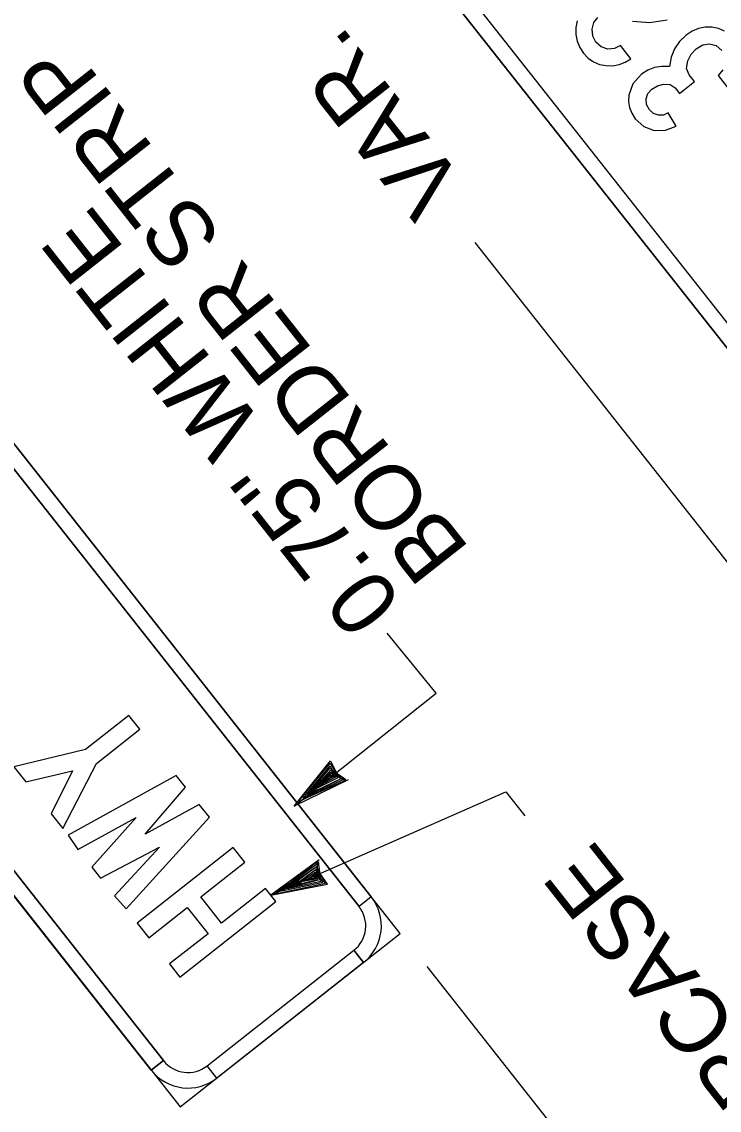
# Model space of a CAD drawing. Extents: x 672239 to 673995, y 1673540 to 1675195.
# Drawn here: x 672381.1 to 672425.9, y 1674877.9 to 1674947.8 of the extents above; entities that cross this region are included whole.
import ezdxf

# ---------------------------------------------------------------- set-up
doc = ezdxf.new("R2010")
doc.units = 0
for name, color, linetype in [('C-ALGN-SYMB', 7, 'Continuous'), ('C-ANNO-SYMB', 7, 'Continuous'), ('C-HELI-TDZM', 7, 'Continuous')]:
    doc.layers.add(name, color=color, linetype=linetype)

msp = doc.modelspace()

# ---------------------------------------------------------------- linework, layer by layer
at = {"layer": 'C-ALGN-SYMB'}
for p, q in [((672430.023, 1674908.599), (672410.262, 1674933.666)), ((672398.641, 1674897.415), (672400.961, 1674900.325)), ((672398.859, 1674897.651), (672400.942, 1674900.177)), ((672400.942, 1674900.177), (672401.284, 1674899.611)), ((672400.961, 1674900.325), (672401.353, 1674899.566)), ((672399.21, 1674897.927), (672400.94, 1674900.008)), ((672399.429, 1674898.027), (672400.983, 1674899.743)), ((672399.5, 1674898.151), (672400.942, 1674899.877)), ((672399.934, 1674898.49), (672400.928, 1674899.599)), ((672400.321, 1674898.759), (672400.892, 1674899.472)), ((672400.986, 1674899.611), (672400.48, 1674898.853)), ((672400.892, 1674899.472), (672401.174, 1674899.326)), ((672400.928, 1674899.599), (672401.281, 1674899.277)), ((672400.94, 1674900.008), (672401.078, 1674899.748)), ((672400.942, 1674899.877), (672401.623, 1674899.179)), ((672400.983, 1674899.743), (672401.443, 1674899.237)), ((672401.362, 1674899.341), (672400.986, 1674899.611)), ((672401.078, 1674899.748), (672401.623, 1674899.179)), ((672401.284, 1674899.611), (672401.955, 1674899.139)), ((672401.353, 1674899.566), (672401.595, 1674899.256)), ((672402.102, 1674899.121), (672398.641, 1674897.415)), ((672401.744, 1674899.107), (672398.901, 1674897.683)), ((672401.909, 1674899.068), (672399.061, 1674897.775)), ((672401.623, 1674899.179), (672399.429, 1674898.027)), ((672401.623, 1674899.179), (672399.5, 1674898.151)), ((672401.443, 1674899.237), (672399.934, 1674898.49)), ((672400.48, 1674898.853), (672400.227, 1674898.752)), ((672401.281, 1674899.277), (672400.321, 1674898.759)), ((672400.657, 1674899.055), (672400.922, 1674899.395)), ((672401.174, 1674899.326), (672400.657, 1674899.055)), ((672400.922, 1674899.395), (672401.004, 1674899.33)), ((672401.004, 1674899.33), (672401.362, 1674899.341)), ((672401.595, 1674899.256), (672401.909, 1674899.068)), ((672401.955, 1674899.139), (672401.735, 1674899.202)), ((672401.735, 1674899.202), (672401.744, 1674899.107)), ((672400.248, 1674893.974), (672397.128, 1674891.704)), ((672400.112, 1674893.828), (672397.642, 1674891.909)), ((672400.132, 1674893.463), (672400.112, 1674893.828)), ((672400.196, 1674893.835), (672400.15, 1674893.612)), ((672400.302, 1674893.022), (672400.196, 1674893.835)), ((672400.069, 1674893.664), (672397.486, 1674891.81)), ((672400.076, 1674893.523), (672398.036, 1674892.117)), ((672400.076, 1674893.523), (672398.179, 1674892.123)), ((672400.045, 1674893.337), (672398.681, 1674892.349)), ((672400.004, 1674893.175), (672399.1, 1674892.566)), ((672399.922, 1674892.906), (672400.099, 1674893.217)), ((672400.125, 1674892.712), (672400.004, 1674893.175)), ((672400.278, 1674892.694), (672400.045, 1674893.337)), ((672400.15, 1674893.612), (672400.069, 1674893.664)), ((672400.327, 1674892.776), (672400.076, 1674893.523)), ((672400.378, 1674892.595), (672400.076, 1674893.523)), ((672400.099, 1674893.217), (672400.163, 1674892.758)), ((672400.294, 1674893.105), (672400.132, 1674893.463)), ((672397.438, 1674891.787), (672400.643, 1674892.457)), ((672397.609, 1674891.979), (672398.357, 1674892.489)), ((672397.846, 1674891.97), (672400.493, 1674892.533)), ((672398.357, 1674892.489), (672397.846, 1674891.97)), ((672398.036, 1674892.117), (672400.278, 1674892.694)), ((672398.179, 1674892.123), (672400.378, 1674892.595)), ((672398.574, 1674892.328), (672398.961, 1674892.617)), ((672399.05, 1674892.486), (672398.574, 1674892.328)), ((672398.681, 1674892.349), (672400.125, 1674892.712)), ((672399.257, 1674892.664), (672399.05, 1674892.486)), ((672399.1, 1674892.566), (672399.996, 1674892.74)), ((672400.163, 1674892.758), (672399.257, 1674892.664)), ((672399.998, 1674893.057), (672399.517, 1674892.726)), ((672399.517, 1674892.726), (672399.942, 1674892.803)), ((672399.942, 1674892.803), (672399.922, 1674892.906)), ((672399.996, 1674892.74), (672399.998, 1674893.057)), ((672400.783, 1674892.404), (672400.294, 1674893.105)), ((672400.643, 1674892.457), (672400.302, 1674893.022)), ((672400.493, 1674892.533), (672400.327, 1674892.776)), ((672397.128, 1674891.704), (672400.783, 1674892.404)), ((672397.642, 1674891.909), (672397.438, 1674891.787)), ((672397.486, 1674891.81), (672397.609, 1674891.979)), ((672407.148, 1674887.119), (672415.977, 1674875.92))]:
    msp.add_line(p, q, dxfattribs=at)
for points in [[(672398.641, 1674897.415), (672407.754, 1674904.676), (672404.616, 1674908.532)], [(672397.128, 1674891.704), (672412.236, 1674898.341), (672413.459, 1674896.791)]]:
    msp.add_lwpolyline(points, dxfattribs=at)
at = {"layer": 'C-ANNO-SYMB'}
for p, q in [((672384.691, 1674979.825), (672436.696, 1674913.859)), ((672387.334, 1674978.088), (672435.624, 1674916.834)), ((672434.839, 1674916.215), (672386.549, 1674977.469)), ((672405.449, 1674889.226), (672372.018, 1674931.633)), ((672405.449, 1674889.226), (672372.018, 1674931.633)), ((672373.875, 1674929.277), (672403.592, 1674891.582)), ((672403.592, 1674891.582), (672373.875, 1674929.277)), ((672402.807, 1674890.963), (672373.09, 1674928.658)), ((672373.09, 1674928.658), (672402.807, 1674890.963)), ((672357.882, 1674920.489), (672391.314, 1674878.082)), ((672357.882, 1674920.489), (672391.314, 1674878.082)), ((672360.525, 1674918.752), (672390.242, 1674881.057)), ((672390.242, 1674881.057), (672360.525, 1674918.752)), ((672389.456, 1674880.438), (672359.739, 1674918.133)), ((672359.739, 1674918.133), (672389.456, 1674880.438)), ((672403.592, 1674891.582), (672402.807, 1674890.963)), ((672403.592, 1674891.582), (672402.807, 1674890.963)), ((672403.592, 1674891.582), (672402.807, 1674890.963)), ((672403.592, 1674891.582), (672402.807, 1674890.963)), ((672402.807, 1674890.963), (672402.807, 1674890.963)), ((672402.807, 1674890.963), (672402.807, 1674890.963)), ((672402.807, 1674890.963), (672402.807, 1674890.963)), ((672402.807, 1674890.963), (672402.807, 1674890.963)), ((672391.314, 1674878.082), (672405.449, 1674889.226)), ((672391.314, 1674878.082), (672405.449, 1674889.226)), ((672405.449, 1674889.226), (672405.449, 1674889.226)), ((672405.449, 1674889.226), (672405.449, 1674889.226)), ((672405.449, 1674889.226), (672405.449, 1674889.226)), ((672405.449, 1674889.226), (672405.449, 1674889.226)), ((672393.05, 1674880.725), (672402.474, 1674888.154)), ((672393.05, 1674880.725), (672402.474, 1674888.154)), ((672402.474, 1674888.154), (672403.093, 1674887.368)), ((672402.474, 1674888.154), (672403.093, 1674887.368)), ((672402.474, 1674888.154), (672403.093, 1674887.368)), ((672403.093, 1674887.368), (672402.474, 1674888.154)), ((672402.474, 1674888.154), (672403.093, 1674887.368)), ((672403.093, 1674887.368), (672393.67, 1674879.939)), ((672403.093, 1674887.368), (672393.67, 1674879.939)), ((672390.242, 1674881.057), (672389.456, 1674880.438)), ((672390.242, 1674881.057), (672389.456, 1674880.438)), ((672390.242, 1674881.057), (672389.456, 1674880.438)), ((672390.242, 1674881.057), (672389.456, 1674880.438)), ((672389.456, 1674880.438), (672390.242, 1674881.057)), ((672393.67, 1674879.939), (672393.05, 1674880.725)), ((672393.67, 1674879.939), (672393.05, 1674880.725)), ((672393.67, 1674879.939), (672393.05, 1674880.725)), ((672393.05, 1674880.725), (672393.05, 1674880.725)), ((672393.05, 1674880.725), (672393.05, 1674880.725)), ((672393.67, 1674879.939), (672393.05, 1674880.725)), ((672393.05, 1674880.725), (672393.05, 1674880.725)), ((672393.05, 1674880.725), (672393.05, 1674880.725))]:
    msp.add_line(p, q, dxfattribs=at)
for points in [[(672416.81, 1674947.911), (672416.727, 1674947.475), (672416.731, 1674947.028), (672416.814, 1674946.604), (672416.982, 1674946.2), (672417.229, 1674945.821), (672417.528, 1674945.508), (672417.868, 1674945.271), (672418.252, 1674945.111), (672418.673, 1674945.03), (672419.109, 1674945.024), (672419.518, 1674945.096), (672419.906, 1674945.246), (672420.265, 1674945.474), (672419.598, 1674946.319), (672419.215, 1674946.122), (672418.776, 1674946.096), (672418.356, 1674946.237), (672418.018, 1674946.533), (672417.819, 1674946.918), (672417.774, 1674947.366), (672417.886, 1674947.795), (672418.15, 1674948.116)], [(672420.362, 1674947.882), (672421.474, 1674947.795), (672422.591, 1674947.966)], [(672426.282, 1674947.248), (672425.895, 1674947.417), (672425.466, 1674947.502), (672425.032, 1674947.502), (672424.611, 1674947.415), (672424.205, 1674947.242), (672423.814, 1674946.986), (672423.389, 1674946.577), (672423.07, 1674946.105), (672422.86, 1674945.572), (672422.755, 1674944.982), (672422.249, 1674944.983), (672421.778, 1674944.901), (672421.346, 1674944.731), (672420.948, 1674944.475), (672420.398, 1674943.867), (672420.13, 1674943.136), (672420.11, 1674942.727), (672420.171, 1674942.338), (672420.318, 1674941.965), (672420.548, 1674941.611), (672421.102, 1674941.11), (672421.77, 1674940.862), (672422.483, 1674940.87), (672423.166, 1674941.146), (672422.659, 1674942.001), (672422.354, 1674941.852), (672422.034, 1674941.835), (672421.727, 1674941.949), (672421.459, 1674942.195), (672421.275, 1674942.538), (672421.239, 1674942.899), (672421.353, 1674943.236), (672421.603, 1674943.519), (672421.966, 1674943.735), (672422.365, 1674943.845), (672422.797, 1674943.811), (672423.101, 1674943.592), (672423.379, 1674943.239), (672424.346, 1674944.001), (672424.003, 1674944.435), (672423.844, 1674944.839), (672423.922, 1674945.338), (672424.143, 1674945.776), (672424.462, 1674946.116), (672424.885, 1674946.361), (672425.308, 1674946.431), (672425.74, 1674946.313), (672426.106, 1674945.992)], [(672426.171, 1674944.749), (672425.875, 1674944.39), (672426.566, 1674943.514)]]:
    msp.add_lwpolyline(points, dxfattribs=at)
for points in [[(672381.395, 1674898.989), (672384.395, 1674899.691), (672383.028, 1674896.917), (672383.772, 1674895.974), (672385.932, 1674900.165), (672388.723, 1674902.366), (672388.023, 1674903.255), (672385.231, 1674901.054), (672380.636, 1674899.951)], [(672381.395, 1674898.989), (672384.395, 1674899.691), (672383.028, 1674896.917), (672383.772, 1674895.974), (672385.932, 1674900.165), (672388.723, 1674902.366), (672388.023, 1674903.255), (672385.231, 1674901.054), (672380.636, 1674899.951)], [(672393.187, 1674896.704), (672392.538, 1674897.527), (672389.068, 1674895.612), (672391.662, 1674898.638), (672391.063, 1674899.398), (672384.111, 1674895.543), (672384.745, 1674894.635), (672388.487, 1674896.698), (672385.647, 1674893.491), (672386.195, 1674892.796), (672389.99, 1674894.791), (672387.092, 1674891.658), (672387.833, 1674890.822)], [(672393.187, 1674896.704), (672392.538, 1674897.527), (672389.068, 1674895.612), (672391.662, 1674898.638), (672391.063, 1674899.398), (672384.111, 1674895.543), (672384.745, 1674894.635), (672388.487, 1674896.698), (672385.647, 1674893.491), (672386.195, 1674892.796), (672389.99, 1674894.791), (672387.092, 1674891.658), (672387.833, 1674890.822)], [(672397.461, 1674891.282), (672396.795, 1674892.127), (672393.967, 1674889.898), (672392.634, 1674891.59), (672395.461, 1674893.819), (672394.719, 1674894.761), (672388.558, 1674889.903), (672389.3, 1674888.962), (672391.771, 1674890.91), (672393.105, 1674889.218), (672390.634, 1674887.27), (672391.3, 1674886.425)], [(672397.461, 1674891.282), (672396.795, 1674892.127), (672393.967, 1674889.898), (672392.634, 1674891.59), (672395.461, 1674893.819), (672394.719, 1674894.761), (672388.558, 1674889.903), (672389.3, 1674888.962), (672391.771, 1674890.91), (672393.105, 1674889.218), (672390.634, 1674887.27), (672391.3, 1674886.425)]]:
    msp.add_lwpolyline(points, close=True, dxfattribs=at)
for centre, radius, start, end in [((672401.236, 1674889.724), 3, 308.25039, 38.2506), ((672401.236, 1674889.724), 3, 308.25039, 38.2506), ((672401.236, 1674889.724), 2, 308.25039, 38.2506), ((672401.236, 1674889.724), 2, 308.25039, 38.2506), ((672391.812, 1674882.295), 2, 218.25075, 308.25039), ((672391.812, 1674882.295), 2, 218.25075, 308.25039), ((672391.812, 1674882.295), 3, 218.25075, 308.25039), ((672391.812, 1674882.295), 3, 218.25075, 308.25039)]:
    msp.add_arc(centre, radius, start, end, dxfattribs=at)
at = {"layer": 'C-HELI-TDZM'}
msp.add_lwpolyline([(672409.162, 1674896.355), (672409.162, 1674896.355), (672409.162, 1674896.355)], dxfattribs=at)

# ---------------------------------------------------------------- texts
at = {"layer": 'C-ALGN-SYMB'}
for s, p in [('VAR.', (672409.709, 1674937.416)), ('BORDER STRIP', (672409.98, 1674913.929)), ('0.75" WHITE ', (672405.686, 1674910.543)), ('8" UPPERCASE', (672443.38, 1674862.843))]:
    msp.add_text(s, height=4.2, rotation=128.25054, dxfattribs=at).set_placement(p)

doc.saveas('drawing.dxf')
